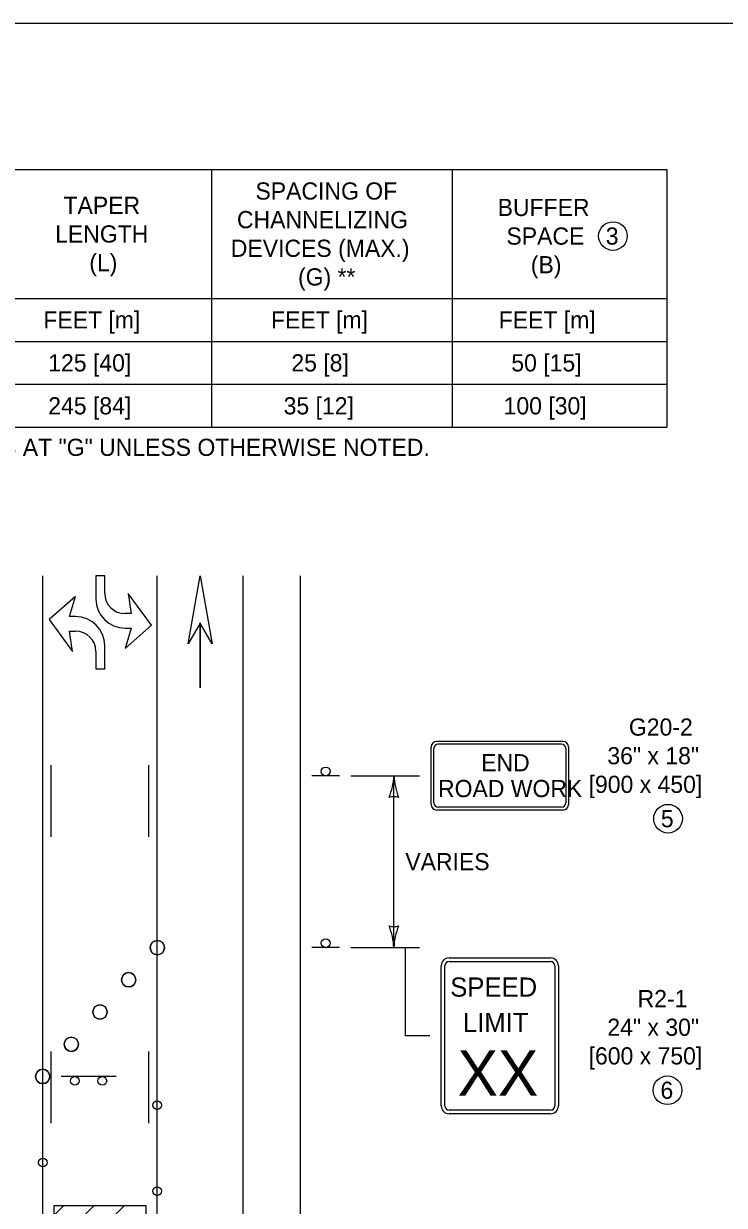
# Model space of a CAD drawing. Extents: x 49991.4 to 50021, y 49987.6 to 50011.4.
# Drawn here: x 50002.813 to 50005.26, y 50007.137 to 50011.263 of the extents above; entities that cross this region are included whole.
import ezdxf

# ---------------------------------------------------------------- set-up
doc = ezdxf.new("R2010")
doc.units = 0
for name, color, linetype in [('Level 1', 7, 'Continuous'), ('Level 2', 7, 'Continuous'), ('Level 3', 7, 'Continuous')]:
    doc.layers.add(name, color=color, linetype=linetype)

msp = doc.modelspace()

# ---------------------------------------------------------------- linework, layer by layer
at = {"layer": 'Level 1'}
for p, q in [((50002.8797, 50000.3857), (50002.8797, 50009.3344)), ((50003.0963, 50009.3343), (50003.0656, 50009.3343)), ((50003.0656, 50009.3343), (50003.0656, 50009.2535)), ((50003.0963, 50009.2737), (50003.0963, 50009.3343)), ((50003.2797, 50000.3857), (50003.2797, 50009.3344)), ((50003.5797, 50000.3857), (50003.5797, 50009.3344)), ((50003.7797, 50000.3857), (50003.7797, 50009.3344)), ((50002.9942, 50009.263), (50002.9023, 50009.1822)), ((50002.9738, 50009.1923), (50002.9942, 50009.263)), ((50003.2596, 50009.1625), (50003.1779, 50009.2737)), ((50003.1779, 50009.2737), (50003.1881, 50009.2029)), ((50003.1617, 50009.208), (50003.1617, 50009.208)), ((50003.1881, 50009.2029), (50003.1677, 50009.2029)), ((50002.9023, 50009.1822), (50002.984, 50009.071)), ((50002.9942, 50009.1923), (50002.9738, 50009.1923)), ((50003.1677, 50009.0816), (50003.2596, 50009.1625)), ((50003.4297, 50008.9443), (50003.4297, 50009.1702)), ((50003.4301, 50008.9443), (50003.4301, 50009.1702)), ((50002.984, 50009.071), (50002.9738, 50009.1417)), ((50002.9738, 50009.1417), (50002.9942, 50009.1417)), ((50003.0002, 50009.1367), (50003.0002, 50009.1367)), ((50003.1677, 50009.1524), (50003.1881, 50009.1524)), ((50003.1881, 50009.1524), (50003.1677, 50009.0816)), ((50003.0963, 50009.0103), (50003.0963, 50009.0912)), ((50003.0656, 50009.071), (50003.0656, 50009.0103)), ((50003.0656, 50009.0103), (50003.0963, 50009.0103)), ((50004.6958, 50008.7569), (50004.2558, 50008.7569)), ((50004.6908, 50008.7469), (50004.2608, 50008.7469)), ((50004.2358, 50008.5369), (50004.2358, 50008.7369)), ((50004.2458, 50008.5419), (50004.2458, 50008.7319)), ((50004.7058, 50008.7319), (50004.7058, 50008.5419)), ((50004.7158, 50008.7369), (50004.7158, 50008.5369)), ((50002.9097, 50008.424), (50002.9097, 50008.674)), ((50003.2497, 50008.424), (50003.2497, 50008.674)), ((50003.9157, 50008.6368), (50003.8197, 50008.6368)), ((50004.6957, 50008.5168), (50004.2557, 50008.5168)), ((50004.6908, 50008.5269), (50004.2608, 50008.5269)), ((50003.9157, 50008.0368), (50003.8197, 50008.0368)), ((50004.2712, 50007.484), (50004.2712, 50007.9735)), ((50004.2836, 50007.484), (50004.2836, 50007.9735)), ((50004.2983, 50008.0007), (50004.6528, 50008.0007)), ((50004.2983, 50007.9883), (50004.6528, 50007.9883)), ((50004.6676, 50007.9735), (50004.6676, 50007.484)), ((50004.68, 50007.9735), (50004.68, 50007.484)), ((50002.9097, 50007.424), (50002.9097, 50007.674)), ((50003.2497, 50007.424), (50003.2497, 50007.674)), ((50003.0398, 50007.5868), (50002.9438, 50007.5868)), ((50003.1358, 50007.5868), (50003.0398, 50007.5868)), ((50004.6528, 50007.4692), (50004.2983, 50007.4692)), ((50004.6528, 50007.4568), (50004.2983, 50007.4568)), ((50002.9197, 50007.103), (50002.9535, 50007.1368)), ((50002.9197, 50006.997), (50003.0596, 50007.1368)), ((50002.9197, 50006.8909), (50003.1656, 50007.1368))]:
    msp.add_line(p, q, dxfattribs=at)
for points in [[(50008.6146, 50011.2628), (50000.3356, 50011.2628), (50000.3356, 50000.0624), (50008.6146, 50000.0624)], [(50003.3881, 50009.0979), (50003.4297, 50009.3344), (50003.4717, 50009.0979), (50003.4297, 50009.1701)], [(50003.2397, 50007.1368), (50003.2397, 50004.3368), (50002.9197, 50004.3368), (50002.9197, 50007.1368)]]:
    msp.add_lwpolyline(points, close=True, dxfattribs=at)
for centre, radius in [((50003.8676, 50008.652), 0.0152), ((50003.2797, 50008.0368), 0.025), ((50003.8676, 50008.052), 0.0152), ((50003.1797, 50007.9243), 0.025), ((50003.0797, 50007.8118), 0.025), ((50002.9797, 50007.6993), 0.025), ((50002.8797, 50007.5868), 0.025), ((50002.9918, 50007.5716), 0.0152), ((50003.0878, 50007.5716), 0.0152), ((50003.2797, 50007.4868), 0.015), ((50002.8797, 50007.2868), 0.015), ((50003.2797, 50007.1868), 0.015)]:
    msp.add_circle(centre, radius, dxfattribs=at)
for centre, radius, start, end in [((50004.2558, 50008.7369), 0.02, 90, 180), ((50004.2608, 50008.7319), 0.015, 90, 180), ((50004.6908, 50008.7319), 0.015, 360, 90), ((50004.6958, 50008.7369), 0.02, 360, 90), ((50004.2608, 50008.5419), 0.015, 180, 270), ((50004.6908, 50008.5419), 0.015, 270, 360), ((50004.2557, 50008.5369), 0.02, 180, 270), ((50004.6957, 50008.5369), 0.02, 270, 360), ((50003.2797, 50008.0368), 0.025, 0, 180), ((50003.2797, 50008.0368), 0.025, 180, 0), ((50004.2983, 50007.9735), 0.0272, 90, 180), ((50004.2983, 50007.9735), 0.0148, 90, 180), ((50004.6528, 50007.9735), 0.0272, 0, 90), ((50004.6528, 50007.9735), 0.0148, 0, 90), ((50003.1797, 50007.9243), 0.025, 0, 180), ((50003.1797, 50007.9243), 0.025, 180, 0), ((50003.0797, 50007.8118), 0.025, 0, 180), ((50003.0797, 50007.8118), 0.025, 180, 0), ((50002.9797, 50007.6993), 0.025, 0, 180), ((50002.9797, 50007.6993), 0.025, 180, 0), ((50002.8797, 50007.5868), 0.025, 0, 180), ((50002.8797, 50007.5868), 0.025, 180, 0), ((50004.2983, 50007.484), 0.0272, 180, 270), ((50004.2983, 50007.484), 0.0148, 180, 270), ((50004.6528, 50007.484), 0.0148, 270, 360), ((50004.6528, 50007.484), 0.0272, 270, 360)]:
    msp.add_arc(centre, radius, start, end, dxfattribs=at)
for centre, major_axis in [((50003.1677, 50009.2535), (-0.1021, 0)), ((50003.1677, 50009.2737), (-0.0715, 0)), ((50002.9942, 50009.0912), (0.1021, 0)), ((50002.9942, 50009.071), (0.0715, 0))]:
    msp.add_ellipse(centre, major_axis=major_axis, ratio=0.990099, start_param=0, end_param=1.570796, dxfattribs=at)
at = {"layer": 'Level 2'}
for p, q in [((50001.129, 50010.7535), (50005.059, 50010.7535)), ((50003.469, 50010.7535), (50003.469, 50009.8535)), ((50004.309, 50010.7535), (50004.309, 50009.8535)), ((50005.059, 50010.7535), (50005.059, 50009.8535)), ((50001.129, 50010.3035), (50005.059, 50010.3035)), ((50001.129, 50010.1535), (50005.059, 50010.1535)), ((50001.129, 50010.0035), (50005.059, 50010.0035)), ((50001.129, 50009.8535), (50005.059, 50009.8535))]:
    msp.add_line(p, q, dxfattribs=at)
for centre in [(50004.8706, 50010.5211), (50005.063, 50008.4869), (50005.061, 50007.5388)]:
    msp.add_circle(centre, 0.0501, dxfattribs=at)
at = {"layer": 'Level 3'}
for p, q in [((50003.9557, 50008.6368), (50004.1958, 50008.6369)), ((50004.1057, 50008.0368), (50004.1057, 50008.6369)), ((50003.9557, 50008.0368), (50004.1957, 50008.0368)), ((50004.2312, 50007.7288), (50004.1457, 50007.7288))]:
    msp.add_line(p, q, dxfattribs=at)
msp.add_lwpolyline([(50004.1457, 50008.0368), (50004.1457, 50007.7288)], dxfattribs=at)
for centre, radius, start, end in [((50003.8836, 50008.646), 0.2223, 337.456, 357.6395), ((50004.3384, 50008.6483), 0.233, 182.8273, 202.0772), ((50004.1057, 50008.5086), 0.0548, 72.1388, 107.8612), ((50004.1057, 50008.1651), 0.0548, 252.1388, 287.8612), ((50003.873, 50008.0253), 0.233, 2.8273, 22.0772), ((50004.3278, 50008.0277), 0.2223, 157.456, 177.6395)]:
    msp.add_arc(centre, radius, start, end, dxfattribs=at)

# ---------------------------------------------------------------- texts
at = {"layer": 'Level 1'}
for s, p in [('END', (50004.4106, 50008.6522)), ('ROAD WORK', (50004.2599, 50008.5622))]:
    msp.add_text(s, height=0.06, rotation=360, dxfattribs=at).set_placement(p)
for s, height, p in [('SPEED', 0.06696, (50004.3025, 50007.8656)), ('LIMIT', 0.06696, (50004.3468, 50007.7418)), ('XX', 0.15775, (50004.3285, 50007.5198))]:
    msp.add_text(s, height=height, dxfattribs=at).set_placement(p)
at = {"layer": 'Level 2'}
for s, p in [('SPACING OF', (50003.6225, 50010.6485)), ('TAPER', (50002.9523, 50010.5985)), ('BUFFER', (50004.468, 50010.5911)), ('CHANNELIZING', (50003.5578, 50010.5485)), ('LENGTH', (50002.9231, 50010.4985)), ('SPACE', (50004.4988, 50010.4911)), ('3', (50004.8456, 50010.4912)), ('DEVICES (MAX.)', (50003.5364, 50010.4485)), ('(L)', (50003.0424, 50010.3985)), ('(B)', (50004.5839, 50010.3911)), ('(G) **', (50003.7711, 50010.3485)), ('FEET [m]', (50002.8818, 50010.1985)), ('FEET [m]', (50003.6767, 50010.1985)), ('FEET [m]', (50004.4718, 50010.1985)), ('125 [40]', (50002.8989, 50010.0485)), ('25 [8]', (50003.7478, 50010.0485)), ('50 [15]', (50004.5158, 50010.0485)), ('245 [84]', (50002.8989, 50009.8985)), ('35 [12]', (50003.7208, 50009.8985)), ('100 [30]', (50004.4889, 50009.8985)), ('** SPACE ALL CHANNELIZING DEVICES AT "G" UNLESS OTHERWISE NOTED.', (50001.2718, 50009.7535)), ('G20-2', (50004.9263, 50008.7769)), ('36" x 18"', (50004.8511, 50008.6769)), ('[900 x 450]', (50004.7856, 50008.5769)), ('5', (50005.038, 50008.4569)), ('R2-1', (50004.9567, 50007.8288)), ('24" x 30"', (50004.8511, 50007.7288)), ('[600 x 750]', (50004.7856, 50007.6288)), ('6', (50005.0365, 50007.5088))]:
    msp.add_text(s, height=0.06, dxfattribs=at).set_placement(p)
msp.add_text('VARIES', height=0.06, rotation=360, dxfattribs=at).set_placement((50004.1457, 50008.3068))

doc.saveas('drawing.dxf')
